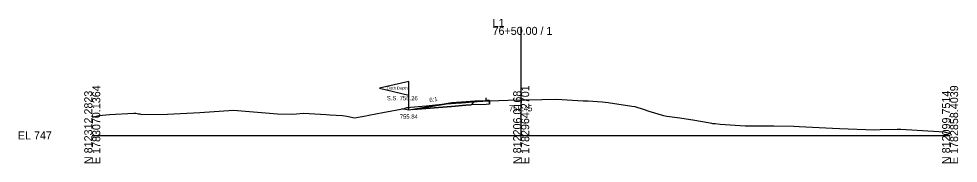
# Model space of a CAD drawing. Extents: x 5574 to 10203, y -10 to 9546.
# Drawn here: x 8574.3 to 8902.8, y 4490.3 to 4540.7 of the extents above; entities that cross this region are included whole.
import ezdxf

# ---------------------------------------------------------------- set-up
doc = ezdxf.new("R2010")
doc.units = 0
for name, color, linetype in [('Exist Cross Section Cell', 7, 'Continuous'), ('Exist XS Center Line Elevation Label', 7, 'Continuous'), ('Exist XS Ground Line', 7, 'Continuous'), ('Prop XS Ditch Slope Text', 7, 'Continuous'), ('Prop XS Ditch Standard Text', 7, 'Continuous'), ('Prop XS Dump Level', 7, 'Continuous'), ('Prop XS Earthwork Shape', 7, 'Continuous'), ('Prop XS EOT Tick Mark', 7, 'Continuous'), ('Prop XS Finish Grade', 7, 'Continuous'), ('Prop XS Finish Grade Earthwork', 7, 'Continuous'), ('Prop XS Finish Grade Paved Shoulder', 7, 'Continuous'), ('Prop XS Finish Grade Pavement', 7, 'Continuous'), ('Prop XS Hydro Typical Ditch Data', 7, 'Continuous'), ('Prop XS Pvmt Edge Slope', 7, 'Continuous'), ('Prop XS SS Elevation Text', 7, 'Continuous'), ('Prop XS Subgrade Earthwork', 7, 'Continuous'), ('Scratch_Level_3', 7, 'Continuous'), ('Scratch_Level_6', 7, 'Continuous')]:
    doc.layers.add(name, color=color, linetype=linetype)

msp = doc.modelspace()

# ---------------------------------------------------------------- linework, layer by layer
at = {"layer": 'Exist Cross Section Cell'}
for p, q in [((8750, 4500), (8750, 4537.9)), ((8600, 4500), (8750, 4500)), ((8750, 4500), (8900, 4500))]:
    msp.add_line(p, q, dxfattribs=at)
at = {"layer": 'Exist XS Ground Line'}
for p, q in [((8716.75, 4510.31), (8722.25, 4510.9)), ((8722.25, 4510.9), (8723.26, 4510.98)), ((8723.26, 4510.98), (8728.63, 4511.34)), ((8728.63, 4511.34), (8729.15, 4511.37)), ((8729.15, 4511.37), (8734.66, 4511.88)), ((8734.66, 4511.88), (8736.58, 4511.99)), ((8736.58, 4511.99), (8738.91, 4512.13)), ((8738.91, 4512.13), (8745.48, 4512.32)), ((8745.48, 4512.32), (8750, 4512.45)), ((8750, 4512.45), (8751.32, 4512.48)), ((8751.32, 4512.48), (8757.22, 4512.56)), ((8757.22, 4512.56), (8762.3, 4512.63)), ((8762.3, 4512.63), (8764.18, 4512.56)), ((8764.18, 4512.56), (8766.09, 4512.47)), ((8766.09, 4512.47), (8771.73, 4512.12)), ((8771.73, 4512.12), (8773.4, 4512.02)), ((8773.4, 4512.02), (8778.37, 4511.71)), ((8778.37, 4511.71), (8780.44, 4511.47)), ((8780.44, 4511.47), (8788.68, 4510.25)), ((8606.03, 4507.31), (8614.52, 4507.77)), ((8614.52, 4507.77), (8615.2, 4507.74)), ((8615.2, 4507.74), (8616.17, 4507.55)), ((8616.17, 4507.55), (8616.69, 4507.55)), ((8616.69, 4507.55), (8617.23, 4507.26)), ((8626.31, 4507.44), (8637.59, 4507.99)), ((8637.59, 4507.99), (8649.39, 4508.81)), ((8649.39, 4508.81), (8664.8, 4507.55)), ((8664.8, 4507.55), (8669.63, 4507.46)), ((8669.63, 4507.46), (8671.39, 4507.56)), ((8671.39, 4507.56), (8673.88, 4507.71)), ((8673.88, 4507.71), (8681.8, 4507.28)), ((8696.67, 4507.08), (8701.6, 4508.05)), ((8701.6, 4508.05), (8709.25, 4509.44)), ((8709.25, 4509.44), (8710.06, 4509.69)), ((8710.06, 4509.69), (8710.55, 4509.75)), ((8710.55, 4509.75), (8711.32, 4509.83)), ((8711.32, 4509.83), (8716.75, 4510.31)), ((8788.68, 4510.25), (8789.77, 4510.1)), ((8789.77, 4510.1), (8792.96, 4508.99)), ((8792.96, 4508.99), (8794.67, 4508.41)), ((8794.67, 4508.41), (8799.79, 4507.01)), ((8600, 4506.47), (8600.4, 4506.53)), ((8600.4, 4506.53), (8602.34, 4506.98)), ((8602.34, 4506.98), (8606.03, 4507.31)), ((8617.23, 4507.26), (8626.31, 4507.44)), ((8681.8, 4507.28), (8683.07, 4507.21)), ((8683.07, 4507.21), (8687.55, 4506.94)), ((8687.55, 4506.94), (8689.08, 4506.73)), ((8689.08, 4506.73), (8691.74, 4506.18)), ((8691.74, 4506.18), (8695.65, 4506.89)), ((8695.65, 4506.89), (8696.67, 4507.08)), ((8799.79, 4507.01), (8800.89, 4506.77)), ((8800.89, 4506.77), (8805.48, 4506.15)), ((8805.48, 4506.15), (8809.27, 4505.56)), ((8809.27, 4505.56), (8809.99, 4505.43)), ((8809.99, 4505.43), (8816.1, 4504.39)), ((8816.1, 4504.39), (8816.52, 4504.32)), ((8816.52, 4504.32), (8816.96, 4504.21)), ((8816.96, 4504.21), (8817.37, 4504.14)), ((8817.37, 4504.14), (8817.87, 4504.14)), ((8817.87, 4504.14), (8819.55, 4503.96)), ((8819.55, 4503.96), (8828.37, 4503.37)), ((8828.37, 4503.37), (8838.34, 4503.39)), ((8838.34, 4503.39), (8845.32, 4503.23)), ((8845.32, 4503.23), (8847.23, 4503.13)), ((8847.23, 4503.13), (8858.82, 4502.56)), ((8858.82, 4502.56), (8861.35, 4502.39)), ((8861.35, 4502.39), (8873.62, 4501.99)), ((8873.62, 4501.99), (8875.51, 4502.06)), ((8875.51, 4502.06), (8881.47, 4502.19)), ((8881.47, 4502.19), (8882.74, 4502.14)), ((8882.74, 4502.14), (8896.01, 4501.4)), ((8896.01, 4501.4), (8897.94, 4501.22)), ((8897.94, 4501.22), (8900, 4500.71))]:
    msp.add_line(p, q, dxfattribs=at)
at = {"layer": 'Prop XS Dump Level'}
for p, q in [((8710.76, 4518.84), (8700.46, 4516.44)), ((8710.76, 4514.04), (8710.76, 4518.84)), ((8700.46, 4516.44), (8710.76, 4514.04)), ((8710.76, 4508.84), (8710.76, 4514.04)), ((8738.89, 4512.22), (8737.76, 4512.2))]:
    msp.add_line(p, q, dxfattribs=at)
at = {"layer": 'Prop XS Earthwork Shape'}
msp.add_lwpolyline([(8710.06, 4509.69), (8710.55, 4509.75), (8711.32, 4509.83), (8716.75, 4510.31), (8722.25, 4510.9), (8723.26, 4510.98), (8728.63, 4511.34), (8729.15, 4511.37), (8734.66, 4511.88), (8736.58, 4511.99), (8738.91, 4512.13), (8738.94, 4512.13), (8738.94, 4510.88), (8737.79, 4510.84), (8732.47, 4510.69), (8730.63, 4510.54), (8725.63, 4510.14), (8712.08, 4509.06), (8710.76, 4508.84), (8708.24, 4509.26), (8709.25, 4509.44)], close=True, dxfattribs=at)
at = {"layer": 'Prop XS EOT Tick Mark'}
msp.add_line((8737.76, 4512.09), (8737.76, 4513.09), dxfattribs=at)
at = {"layer": 'Prop XS Finish Grade'}
for p, q in [((8725.76, 4511.34), (8712.08, 4509.06)), ((8730.76, 4511.74), (8725.76, 4511.34)), ((8733.76, 4511.98), (8730.76, 4511.74))]:
    msp.add_line(p, q, dxfattribs=at)
at = {"layer": 'Prop XS Finish Grade Earthwork'}
for p, q in [((8710.76, 4508.84), (8708.24, 4509.26)), ((8712.08, 4509.06), (8710.76, 4508.84))]:
    msp.add_line(p, q, dxfattribs=at)
at = {"layer": 'Prop XS Finish Grade Paved Shoulder'}
msp.add_line((8737.76, 4512.09), (8733.76, 4511.98), dxfattribs=at)
at = {"layer": 'Prop XS Finish Grade Pavement'}
msp.add_line((8738.94, 4512.13), (8737.76, 4512.09), dxfattribs=at)
at = {"layer": 'Prop XS Hydro Typical Ditch Data'}
msp.add_line((8710.76, 4508.84), (8708.24, 4509.26), dxfattribs=at)
at = {"layer": 'Prop XS Pvmt Edge Slope'}
msp.add_line((8733.76, 4511.98), (8732.47, 4510.69), dxfattribs=at)
at = {"layer": 'Prop XS Subgrade Earthwork'}
for p, q in [((8737.79, 4510.84), (8732.47, 4510.69)), ((8738.94, 4510.88), (8737.79, 4510.84)), ((8738.94, 4510.88), (8738.94, 4512.13)), ((8725.63, 4510.14), (8712.08, 4509.06)), ((8730.63, 4510.54), (8725.63, 4510.14)), ((8732.47, 4510.69), (8730.63, 4510.54))]:
    msp.add_line(p, q, dxfattribs=at)
at = {"layer": 'Scratch_Level_3'}
for p, q in [((8725.76, 4511.34), (8712.08, 4509.06)), ((8730.76, 4511.74), (8725.76, 4511.34)), ((8733.76, 4511.98), (8730.76, 4511.74)), ((8732.47, 4510.69), (8733.76, 4511.98)), ((8712.08, 4509.06), (8725.63, 4510.14)), ((8725.63, 4510.14), (8730.63, 4510.54)), ((8730.63, 4510.54), (8732.47, 4510.69))]:
    msp.add_line(p, q, dxfattribs=at)
at = {"layer": 'Scratch_Level_6'}
msp.add_lwpolyline([(8738.94, 4510.88), (8737.79, 4510.84), (8732.47, 4510.69), (8730.63, 4510.54), (8725.63, 4510.14), (8712.08, 4509.06), (8723.89, 4511.02), (8728.63, 4511.34), (8729.15, 4511.37), (8734.66, 4511.88), (8736.58, 4511.99), (8738.91, 4512.13), (8738.94, 4512.13)], close=True, dxfattribs=at)

# ---------------------------------------------------------------- texts
at = {"layer": 'Exist Cross Section Cell'}
for s, p in [('L1', (8740, 4537.9)), ('76+50.00 / 1', (8740, 4535.1)), ('EL 747', (8574, 4498.6))]:
    msp.add_text(s, height=2.8, dxfattribs=at).set_placement(p)
for s, p in [('E 1783070.1364', (8602.8, 4490)), ('N 812312.2823', (8600, 4490)), ('N 812206.0168', (8750, 4490)), ('E 1782964.2701', (8752.8, 4490)), ('N 812099.7514', (8900, 4490)), ('E 1782858.4039', (8902.8, 4490))]:
    msp.add_text(s, height=2.8, rotation=90, dxfattribs=at).set_placement(p)
at = {"layer": 'Exist XS Center Line Elevation Label'}
msp.add_text('759.45', height=2, dxfattribs=at).set_placement((8745.74, 4508.45))
at = {"layer": 'Prop XS Ditch Slope Text'}
msp.add_text('6:1', height=1.5, rotation=9.4623, dxfattribs=at).set_placement((8718.01, 4511.57))
at = {"layer": 'Prop XS Ditch Standard Text'}
msp.add_text('755.84', height=1.5, dxfattribs=at).set_placement((8707.54, 4505.84))
at = {"layer": 'Prop XS Dump Level'}
for s, height, p in [('Ditch Depth', 1, (8703.1, 4516.01)), ('Case4', 0.04, (8725.76, 4511.3)), ('Eop', 0.3, (8738.94, 4511.83))]:
    msp.add_text(s, height=height, dxfattribs=at).set_placement(p)
at = {"layer": 'Prop XS SS Elevation Text'}
msp.add_text('S.S. 756.26', height=1.5, dxfattribs=at).set_placement((8703.01, 4512.26))

doc.saveas('drawing.dxf')
